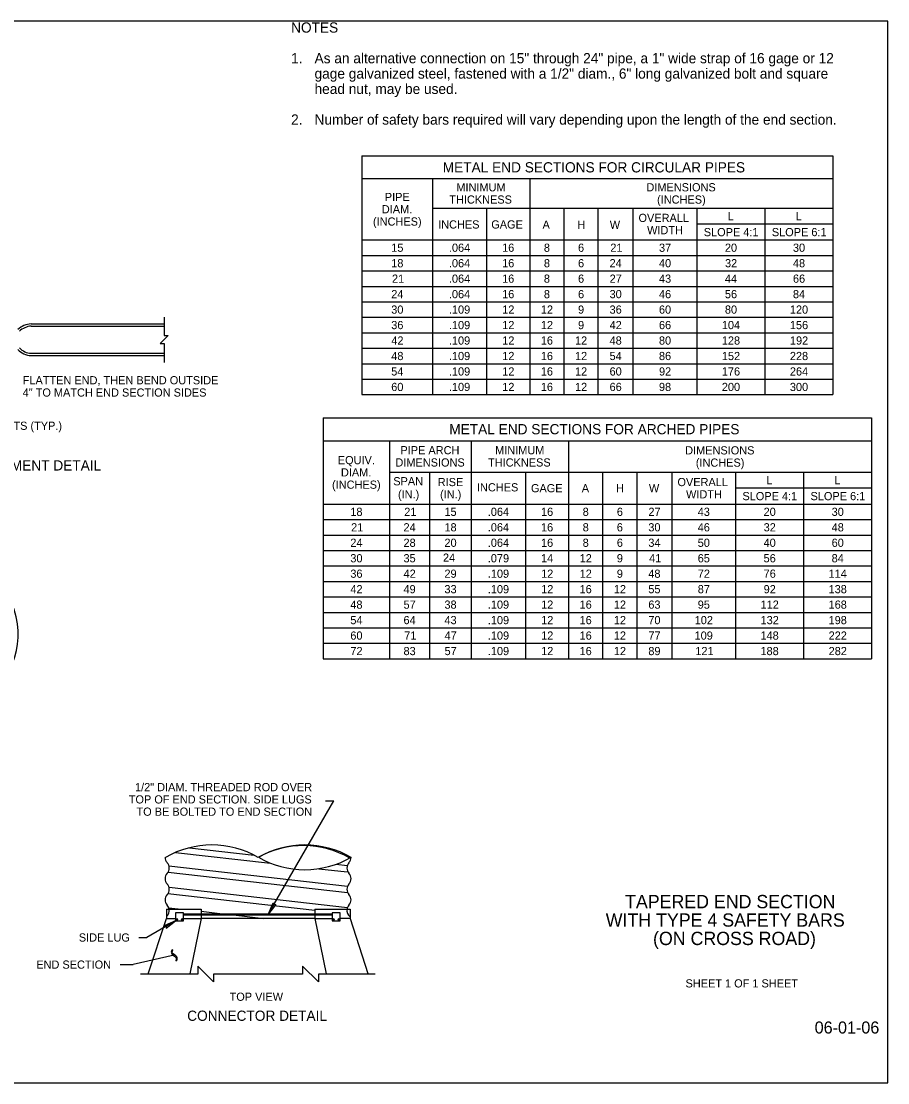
# Model space of a CAD drawing. Extents: x 99862 to 103151, y 100000 to 102076.
# Drawn here: x 101456 to 103151, y 100000 to 102076 of the extents above; entities that cross this region are included whole.
import ezdxf

# ---------------------------------------------------------------- set-up
doc = ezdxf.new("R2010")
doc.units = 0
for name, color, linetype in [('Level 1', 7, 'Continuous'), ('Level 11', 7, 'Continuous'), ('Level 15', 7, 'Continuous'), ('Level 18', 7, 'Continuous'), ('Level 19', 7, 'Continuous'), ('Level 20', 7, 'Continuous'), ('Level 6', 7, 'Continuous'), ('Level 60', 7, 'Continuous'), ('Level 62', 7, 'Continuous'), ('Level 63', 7, 'Continuous')]:
    doc.layers.add(name, color=color, linetype=linetype)

msp = doc.modelspace()

# ---------------------------------------------------------------- linework, layer by layer
at = {"layer": 'Level 1'}
msp.add_lwpolyline([(99862, 99999.5), (103151, 99999.5), (103151, 102075.5), (99862, 102075.5)], close=True, dxfattribs=at)
at = {"layer": 'Level 15'}
for p, q in [((101939.9, 100330), (102067.4, 100550.9)), ((102051.4, 100550.9), (102067.4, 100550.9)), ((101758, 100316.1), (101701.7, 100283.6)), ((101685.7, 100283.6), (101701.7, 100283.6))]:
    msp.add_line(p, q, dxfattribs=at)
for points in [[(101735.4, 101497), (101735.4, 101460.8), (101743.1, 101460.8), (101727.6, 101445.3), (101735.4, 101445.3), (101735.4, 101408)], [(101919.1, 100212.2), (101832, 100212.2), (101832, 100196.7), (101801.1, 100227.7), (101801.1, 100212.2), (101689.5, 100212.2)], [(102148.5, 100212.2), (102037.2, 100212.2), (102037.2, 100196.7), (102006.2, 100227.7), (102006.2, 100212.2), (101919.1, 100212.2)]]:
    msp.add_lwpolyline(points, dxfattribs=at)
for points in [[(101939.9, 100330), (101948.7, 100351.3), (101950.7, 100348.9), (101953.9, 100348.3)], [(101758, 100316.1), (101736.8, 100307.3), (101739.2, 100305.2), (101739.7, 100302.1)]]:
    msp.add_lwpolyline(points, close=True, dxfattribs=at)
at = {"layer": 'Level 18'}
for p, q in [((101475.1, 101483.8), (101734.7, 101483.8)), ((101475.3, 101479.4), (101734.7, 101479.4)), ((101475.1, 101426.2), (101734.7, 101426.2)), ((101475.1, 101421.8), (101734.7, 101421.8)), ((101739.8, 100339.2), (101807.7, 100339.2)), ((101739.8, 100339.2), (101739.8, 100321)), ((101807.7, 100339.2), (101807.7, 100330)), ((102030.3, 100339.2), (102099.4, 100339.2)), ((102030.3, 100339.2), (102030.3, 100330)), ((102099.4, 100339.2), (102099.4, 100321)), ((101704.2, 100212.7), (101739.8, 100321)), ((101773.4, 100330), (102064.3, 100330)), ((101773.4, 100327.6), (102064.3, 100327.6)), ((101807.7, 100321), (101785.8, 100212.5)), ((101807.7, 100327.6), (101807.7, 100321)), ((102030.3, 100327.6), (102030.3, 100321)), ((102030.3, 100321), (102052.2, 100212.5)), ((102099.4, 100321), (102133.7, 100212.9))]:
    msp.add_line(p, q, dxfattribs=at)
for points in [[(101773.4, 100331.6), (101758, 100331.6), (101758, 100316.1), (101773.4, 100316.1)], [(102079.8, 100331.6), (102064.3, 100331.6), (102064.3, 100316.1), (102079.8, 100316.1)]]:
    msp.add_lwpolyline(points, close=True, dxfattribs=at)
for centre, radius, start, end in [((101479, 101439.5), 44.5, 94.9701, 131.9801), ((101479, 101439.5), 40, 94.9701, 131.9801), ((101476.3, 101458.2), 36.5, 222.1687, 268.2497), ((101476.3, 101458.2), 32, 222.1687, 268.2497), ((101760.7, 100318.6), 1.61, 0, 180), ((101760.7, 100318.6), 1.61, 180, 0), ((101770.7, 100318.6), 1.61, 0, 180), ((101770.7, 100318.6), 1.61, 180, 0), ((102067, 100318.6), 1.61, 0, 180), ((102067, 100318.6), 1.61, 180, 0), ((102077.1, 100318.6), 1.61, 0, 180), ((102077.1, 100318.6), 1.61, 180, 0)]:
    msp.add_arc(centre, radius, start, end, dxfattribs=at)
at = {"layer": 'Level 19'}
for p, q in [((102122.4, 101812.4), (103043.6, 101812.4)), ((102122.4, 101812.4), (102122.4, 101345.2)), ((103043.6, 101812.4), (103043.6, 101345.2)), ((102122.4, 101767.8), (103043.6, 101767.8)), ((102260.4, 101767.8), (102260.4, 101345.2)), ((102450.5, 101767.8), (102450.5, 101345.2)), ((102260.4, 101709.7), (103043.6, 101709.7)), ((102365.9, 101709.7), (102365.9, 101345.2)), ((102517.3, 101709.7), (102517.3, 101345.2)), ((102584.1, 101709.7), (102584.1, 101345.2)), ((102652.6, 101709.7), (102652.6, 101345.2)), ((102777.4, 101709.7), (102777.4, 101345.2)), ((102910.7, 101709.7), (102910.7, 101345.2)), ((103043.8, 101678.6), (102777.5, 101678.6)), ((102122.4, 101647.7), (103043.6, 101647.7)), ((102122.4, 101617.5), (103043.6, 101617.5)), ((102122.4, 101587.2), (103043.6, 101587.2)), ((102122.4, 101557), (103043.6, 101557)), ((102122.4, 101526.7), (103043.6, 101526.7)), ((102122.4, 101496.5), (103043.6, 101496.5)), ((102122.4, 101466.2), (103043.6, 101466.2)), ((102122.4, 101436), (103043.6, 101436)), ((102122.4, 101405.7), (103043.6, 101405.7)), ((102122.4, 101375.5), (103043.6, 101375.5)), ((102122.4, 101345.2), (103043.6, 101345.2)), ((102046.6, 101300.2), (102046.6, 100828.7)), ((102046.6, 101300.2), (103119.4, 101300.2)), ((103119.4, 101300.2), (103119.4, 100828.7)), ((102046.6, 101255.2), (103119.4, 101255.2)), ((102176, 101255.2), (102176, 100828.7)), ((102336.2, 101255.2), (102336.2, 100828.7)), ((102526.4, 101255.2), (102526.4, 100828.7)), ((102176, 101193.4), (103119.4, 101193.4)), ((102254.6, 101193.4), (102254.6, 100828.7)), ((102442.4, 101193.4), (102442.4, 100828.7)), ((102593.2, 101193.4), (102593.2, 100828.7)), ((102660, 101193.4), (102660, 100828.7)), ((102728.5, 101193.4), (102728.5, 100828.7)), ((102853.1, 101193.4), (102853.1, 100828.7)), ((102986.3, 101193.4), (102986.3, 100828.7)), ((103119.4, 101162.3), (102853.1, 101162.3)), ((102046.6, 101131.2), (103119.4, 101131.2)), ((102046.6, 101100.9), (103119.4, 101100.9)), ((102046.6, 101070.7), (103119.4, 101070.7)), ((102046.6, 101040.4), (103119.4, 101040.4)), ((102046.6, 101010.2), (103119.4, 101010.2)), ((102046.6, 100979.9), (103119.4, 100979.9)), ((102046.6, 100949.7), (103119.4, 100949.7)), ((102046.6, 100919.4), (103119.4, 100919.4)), ((102046.6, 100889.2), (103119.4, 100889.2)), ((102046.6, 100858.9), (103119.4, 100858.9)), ((102046.6, 100828.7), (103119.4, 100828.7))]:
    msp.add_line(p, q, dxfattribs=at)
at = {"layer": 'Level 20'}
for p, q in [((101749.7, 100257), (101749.4, 100255.2)), ((101749.4, 100255.2), (101749.6, 100253.5)), ((101749.6, 100253.5), (101750.2, 100251.9)), ((101750.4, 100258.8), (101749.7, 100257)), ((101750.2, 100251.9), (101752, 100249.8)), ((101752.2, 100259.8), (101750.4, 100258.8)), ((101751.2, 100255.8), (101751.5, 100257.5)), ((101751.4, 100254.5), (101751.2, 100255.8)), ((101751.9, 100253.2), (101751.4, 100254.5)), ((101751.5, 100257.5), (101752.2, 100259.8)), ((101753.1, 100251.8), (101751.9, 100253.2)), ((101755.2, 100250.3), (101753.1, 100251.8)), ((101758.6, 100248), (101755.2, 100250.3)), ((101649.3, 100230.6), (101674.8, 100230.6)), ((101755.2, 100249), (101674.8, 100230.6)), ((101752, 100249.8), (101755.6, 100247.3)), ((101755.6, 100247.3), (101757.6, 100245.9)), ((101757.6, 100245.9), (101758.5, 100244.7)), ((101759.1, 100241.7), (101758.1, 100238.2)), ((101758.1, 100238.2), (101760, 100239.2)), ((101758.5, 100244.7), (101759, 100243.4)), ((101760.2, 100246.1), (101758.6, 100248)), ((101759, 100243.4), (101759.1, 100241.7)), ((101760, 100239.2), (101760.7, 100241.2)), ((101760.8, 100244.6), (101760.2, 100246.1)), ((101760.7, 100241.2), (101761, 100243)), ((101761, 100243), (101760.8, 100244.6))]:
    msp.add_line(p, q, dxfattribs=at)
at = {"layer": 'Level 6'}
for p, q in [((101784.8, 100459.2), (101911.4, 100444.9)), ((101757.4, 100449.9), (101943.4, 100428.9)), ((101744.9, 100423.5), (102094.3, 100384.1)), ((102038.2, 100418.2), (102093.8, 100411.9)), ((102071.9, 100426.8), (102093.8, 100424.3)), ((101743.1, 100411.4), (102094.3, 100371.7)), ((101745, 100381.8), (102094.1, 100342.3)), ((101743, 100369.6), (102030.3, 100337.2)), ((101744.4, 100341.9), (101768.8, 100339.2)), ((101807.7, 100334.8), (101849.8, 100330)), ((101739.8, 100321), (101758, 100321)), ((101773.4, 100321), (101807.7, 100321)), ((102030.4, 100321), (101807.7, 100321)), ((101871.3, 100327.6), (101929.7, 100321)), ((102030.3, 100321), (102064.3, 100321)), ((102099.4, 100321), (102079.8, 100321))]:
    msp.add_line(p, q, dxfattribs=at)
for centre, radius, start, end in [((101829, 100283.2), 181.4, 60, 120), ((102010.5, 100283.2), 181.4, 60, 120), ((102007.9, 100283), 180.4, 59.8127, 119.2392), ((101752.5, 100440.4), 15.1, 180.0381, 223.1116), ((102010.5, 100597.5), 181.4, 240, 300), ((102086, 100440.4), 15.1, 316.8884, 359.9619), ((101730.4, 100419.5), 15.1, 316.8884, 43.1116), ((102108.1, 100419.5), 15.1, 136.8884, 223.1116), ((101752.5, 100398.8), 15.1, 136.8884, 223.1116), ((102086, 100398.8), 15.1, 316.8884, 43.1116), ((101730.4, 100377.9), 15.1, 316.8884, 43.1116), ((102108.1, 100377.9), 15.1, 136.8884, 223.1116), ((101752.5, 100357.2), 15.1, 136.8884, 223.1116), ((102086, 100357.2), 15.1, 316.8884, 43.1116), ((101730.4, 100336.3), 15.1, 308.3919, 10.768), ((101730.4, 100336.3), 15.1, 10.768, 43.1116), ((102108.1, 100336.5), 15.1, 169.9575, 234.8817), ((102108.1, 100336.5), 15.1, 136.8884, 169.9575)]:
    msp.add_arc(centre, radius, start, end, dxfattribs=at)
msp.add_ellipse((101299.1, 100908.9), major_axis=(-114.1, 124), ratio=0.796016, start_param=2.847597, end_param=5.706242, dxfattribs=at)
at = {"layer": 'Level 60'}
msp.add_line((103151, 102075.5), (103151, 102075.5), dxfattribs=at)

# ---------------------------------------------------------------- texts
at = {"layer": 'Level 11'}
msp.add_text('06-01-06', height=23.62, dxfattribs=at).set_placement((103008, 100095.8))
at = {"layer": 'Level 19'}
for s, height, p in [('METAL END SECTIONS FOR CIRCULAR PIPES', 20, (102280.4, 101779.8)), ('MINIMUM', 16, (102307.1, 101742.8)), ('DIMENSIONS', 16, (102678.9, 101742.8)), ('PIPE', 16, (102167.2, 101723.8)), ('THICKNESS', 16, (102293.3, 101718.8)), ('(INCHES)', 16, (102699.7, 101718.8)), ('DIAM.', 16, (102161.3, 101699.8)), ('(INCHES)', 16, (102144, 101675.8)), ('INCHES', 16, (102271.5, 101670.1)), ('GAGE', 16, (102375.4, 101670.1)), ('A', 16, (102475.7, 101669.7)), ('H', 16, (102543.8, 101669.3)), ('W', 16, (102607.2, 101669.5)), ('OVERALL', 16, (102663.4, 101682.9)), ('L', 16, (102837.8, 101686.2)), ('L', 16, (102970.9, 101686.2)), ('WIDTH', 16, (102680.2, 101658.9)), ('SLOPE 4:1', 16, (102791.1, 101655.1)), ('SLOPE 6:1', 16, (102924.2, 101655.1)), ('15', 16, (102179.7, 101624.6)), ('.064', 16, (102292.5, 101624.6)), ('16', 16, (102396.6, 101624.6)), ('8', 16, (102478.3, 101624.6)), ('6', 16, (102545.1, 101624.6)), ('21', 16, (102608.3, 101624.6)), ('37', 16, (102703.5, 101624.6)), ('20', 16, (102832.4, 101624.6)), ('30', 16, (102965.5, 101624.6)), ('18', 16, (102179.7, 101594.3)), ('.064', 16, (102292.5, 101594.3)), ('16', 16, (102396.6, 101594.3)), ('8', 16, (102478.3, 101594.3)), ('6', 16, (102545.1, 101594.3)), ('24', 16, (102606.8, 101594.3)), ('40', 16, (102703.4, 101594.3)), ('32', 16, (102832.6, 101594.3)), ('48', 16, (102965.5, 101594.3)), ('21', 16, (102181.2, 101564.1)), ('.064', 16, (102292.5, 101564.1)), ('16', 16, (102396.6, 101564.1)), ('8', 16, (102478.3, 101564.1)), ('6', 16, (102545.1, 101564.1)), ('27', 16, (102606.9, 101564.1)), ('43', 16, (102703.4, 101564.1)), ('44', 16, (102832.4, 101564.1)), ('66', 16, (102965.5, 101564.1)), ('24', 16, (102179.7, 101533.8)), ('.064', 16, (102292.5, 101533.8)), ('16', 16, (102396.6, 101533.8)), ('8', 16, (102478.3, 101533.8)), ('6', 16, (102545.1, 101533.8)), ('30', 16, (102606.8, 101533.8)), ('46', 16, (102703.4, 101533.8)), ('56', 16, (102832.4, 101533.8)), ('84', 16, (102965.5, 101533.8)), ('30', 16, (102179.7, 101503.6)), ('.109', 16, (102292.5, 101503.6)), ('12', 16, (102396.8, 101503.6)), ('12', 16, (102472.4, 101503.6)), ('9', 16, (102545.1, 101503.6)), ('36', 16, (102606.8, 101503.6)), ('60', 16, (102703.4, 101503.6)), ('80', 16, (102832.4, 101503.6)), ('120', 16, (102959.5, 101503.6)), ('36', 16, (102179.7, 101473.3)), ('.109', 16, (102292.5, 101473.3)), ('12', 16, (102396.8, 101473.3)), ('12', 16, (102472.4, 101473.3)), ('9', 16, (102545.1, 101473.3)), ('42', 16, (102606.9, 101473.3)), ('66', 16, (102703.4, 101473.3)), ('104', 16, (102826.4, 101473.3)), ('156', 16, (102959.5, 101473.3)), ('42', 16, (102179.9, 101443.1)), ('.109', 16, (102292.5, 101443.1)), ('12', 16, (102396.8, 101443.1)), ('16', 16, (102472.3, 101443.1)), ('12', 16, (102539.2, 101443.1)), ('48', 16, (102606.8, 101443.1)), ('80', 16, (102703.4, 101443.1)), ('128', 16, (102826.4, 101443.1)), ('192', 16, (102959.6, 101443.1)), ('48', 16, (102179.7, 101412.8)), ('.109', 16, (102292.5, 101412.8)), ('12', 16, (102396.8, 101412.8)), ('16', 16, (102472.3, 101412.8)), ('12', 16, (102539.2, 101412.8)), ('54', 16, (102606.8, 101412.8)), ('86', 16, (102703.4, 101412.8)), ('152', 16, (102826.5, 101412.8)), ('228', 16, (102959.5, 101412.8)), ('54', 16, (102179.7, 101382.6)), ('.109', 16, (102292.5, 101382.6)), ('12', 16, (102396.8, 101382.6)), ('16', 16, (102472.3, 101382.6)), ('12', 16, (102539.2, 101382.6)), ('60', 16, (102606.8, 101382.6)), ('92', 16, (102703.5, 101382.6)), ('176', 16, (102826.4, 101382.6)), ('264', 16, (102959.5, 101382.6)), ('60', 16, (102179.7, 101352.3)), ('.109', 16, (102292.5, 101352.3)), ('12', 16, (102396.8, 101352.3)), ('16', 16, (102472.3, 101352.3)), ('12', 16, (102539.2, 101352.3)), ('66', 16, (102606.8, 101352.3)), ('98', 16, (102703.4, 101352.3)), ('200', 16, (102826.4, 101352.3)), ('300', 16, (102959.5, 101352.3)), ('METAL END SECTIONS FOR ARCHED PIPES', 20, (102293.2, 101267.7)), ('PIPE ARCH', 16, (102197.7, 101228.6)), ('MINIMUM', 16, (102383, 101228.6)), ('DIMENSIONS', 16, (102754.7, 101228.3)), ('EQUIV.', 16, (102075.2, 101209.2)), ('DIMENSIONS', 16, (102187.9, 101204.6)), ('THICKNESS', 16, (102369.1, 101204.6)), ('(INCHES)', 16, (102775.5, 101204.3)), ('DIAM.', 16, (102081.3, 101185.2)), ('L', 16, (102913.4, 101169.9)), ('L', 16, (103046.5, 101169.9)), ('(INCHES)', 16, (102063.9, 101161.2)), ('SPAN', 16, (102183.7, 101167.9)), ('RISE', 16, (102270.7, 101166.3)), ('INCHES', 16, (102347.4, 101156)), ('GAGE', 16, (102453, 101154.3)), ('A', 16, (102552.4, 101154.3)), ('H', 16, (102619.5, 101154.3)), ('W', 16, (102683.8, 101154.3)), ('OVERALL', 16, (102739.6, 101166.3)), ('(IN.)', 16, (102192.9, 101142.3)), ('(IN.)', 16, (102275.2, 101142.3)), ('WIDTH', 16, (102756.4, 101142.3)), ('SLOPE 4:1', 16, (102866.7, 101138.8)), ('SLOPE 6:1', 16, (102999.9, 101138.8)), ('18', 16, (102099.7, 101108.1)), ('21', 16, (102205.2, 101108.1)), ('15', 16, (102283.8, 101108.1)), ('.064', 16, (102368.6, 101108.1)), ('16', 16, (102472.7, 101108.1)), ('8', 16, (102554.2, 101108.1)), ('6', 16, (102621, 101108.1)), ('27', 16, (102682.8, 101108.1)), ('43', 16, (102779.2, 101108.1)), ('20', 16, (102908.1, 101108.1)), ('30', 16, (103041.2, 101108.1)), ('21', 16, (102101.2, 101077.8)), ('24', 16, (102203.7, 101077.8)), ('18', 16, (102283.8, 101077.8)), ('.064', 16, (102368.6, 101077.8)), ('16', 16, (102472.7, 101077.8)), ('8', 16, (102554.2, 101077.8)), ('6', 16, (102621, 101077.8)), ('30', 16, (102682.6, 101077.8)), ('46', 16, (102779.2, 101077.8)), ('32', 16, (102908.2, 101077.8)), ('48', 16, (103041.2, 101077.8)), ('24', 16, (102099.7, 101047.6)), ('28', 16, (102203.7, 101047.6)), ('20', 16, (102283.8, 101047.6)), ('.064', 16, (102368.6, 101047.6)), ('16', 16, (102472.7, 101047.6)), ('8', 16, (102554.2, 101047.6)), ('6', 16, (102621, 101047.6)), ('34', 16, (102682.6, 101047.6)), ('50', 16, (102779.2, 101047.6)), ('40', 16, (102908.1, 101047.6)), ('60', 16, (103041.2, 101047.6)), ('30', 16, (102099.7, 101017.3)), ('35', 16, (102203.7, 101017.3)), ('24', 16, (102280.9, 101018.5)), ('.079', 16, (102368.6, 101017.3)), ('14', 16, (102472.7, 101017.3)), ('12', 16, (102548.3, 101017.3)), ('9', 16, (102621, 101017.3)), ('41', 16, (102684.1, 101017.3)), ('65', 16, (102779.2, 101017.3)), ('56', 16, (102908.1, 101017.3)), ('84', 16, (103041.2, 101017.3)), ('36', 16, (102099.7, 100987.1)), ('42', 16, (102203.8, 100987.1)), ('29', 16, (102283.8, 100987.1)), ('.109', 16, (102368.6, 100987.1)), ('12', 16, (102472.9, 100987.1)), ('12', 16, (102548.3, 100987.1)), ('9', 16, (102621, 100987.1)), ('48', 16, (102682.6, 100987.1)), ('72', 16, (102779.3, 100987.1)), ('76', 16, (102908.1, 100987.1)), ('114', 16, (103035.2, 100987.1)), ('42', 16, (102099.8, 100956.8)), ('49', 16, (102203.7, 100956.8)), ('33', 16, (102283.8, 100956.8)), ('.109', 16, (102368.6, 100956.8)), ('12', 16, (102472.9, 100956.8)), ('16', 16, (102548.1, 100956.8)), ('12', 16, (102615.1, 100956.8)), ('55', 16, (102682.6, 100956.8)), ('87', 16, (102779.3, 100956.8)), ('92', 16, (102908.2, 100956.8)), ('138', 16, (103035.2, 100956.8)), ('48', 16, (102099.7, 100926.6)), ('57', 16, (102203.8, 100926.6)), ('38', 16, (102283.8, 100926.6)), ('.109', 16, (102368.6, 100926.6)), ('12', 16, (102472.9, 100926.6)), ('16', 16, (102548.1, 100926.6)), ('12', 16, (102615.1, 100926.6)), ('63', 16, (102682.6, 100926.6)), ('95', 16, (102779.2, 100926.6)), ('112', 16, (102902.2, 100926.6)), ('168', 16, (103035.2, 100926.6)), ('54', 16, (102099.7, 100896.3)), ('64', 16, (102203.7, 100896.3)), ('43', 16, (102283.8, 100896.3)), ('.109', 16, (102368.6, 100896.3)), ('12', 16, (102472.9, 100896.3)), ('16', 16, (102548.1, 100896.3)), ('12', 16, (102615.1, 100896.3)), ('70', 16, (102682.6, 100896.3)), ('102', 16, (102773.3, 100896.3)), ('132', 16, (102902.2, 100896.3)), ('198', 16, (103035.2, 100896.3)), ('60', 16, (102099.7, 100866.1)), ('71', 16, (102205.2, 100866.1)), ('47', 16, (102284, 100866.1)), ('.109', 16, (102368.6, 100866.1)), ('12', 16, (102472.9, 100866.1)), ('16', 16, (102548.1, 100866.1)), ('12', 16, (102615.1, 100866.1)), ('77', 16, (102682.8, 100866.1)), ('109', 16, (102773.1, 100866.1)), ('148', 16, (102902, 100866.1)), ('222', 16, (103035.3, 100866.1)), ('72', 16, (102099.8, 100835.8)), ('83', 16, (102203.7, 100835.8)), ('57', 16, (102284, 100835.8)), ('.109', 16, (102368.6, 100835.8)), ('12', 16, (102472.9, 100835.8)), ('16', 16, (102548.1, 100835.8)), ('12', 16, (102615.1, 100835.8)), ('89', 16, (102682.6, 100835.8)), ('121', 16, (102774.6, 100835.8)), ('188', 16, (102902, 100835.8)), ('282', 16, (103035.3, 100835.8))]:
    msp.add_text(s, height=height, dxfattribs=at).set_placement(p)
at = {"layer": 'Level 20'}
for s, height, p in [('NOTES', 20, (101983.8, 102053.2)), ('1.', 20, (101983.8, 101993.2)), ('As an alternative connection on 15" through 24" pipe, a 1" wide strap of 16 gage or 12', 20, (102029.7, 101993.2)), ('gage galvanized steel, fastened with a 1/2" diam., 6" long galvanized bolt and square', 20, (102029.7, 101963.2)), ('head nut, may be used.', 20, (102029.7, 101933.2)), ('2.', 20, (101983.8, 101873.2)), ('Number of safety bars required will vary depending upon the length of the end section.', 20, (102029.7, 101873.2)), ('FLATTEN END, THEN BEND OUTSIDE', 16, (101458.8, 101365.4)), ('4" TO MATCH END SECTION SIDES', 16, (101458.8, 101341.4)), ('9/16" x 1" SLOTS (TYP.)', 16, (101300.6, 101276.4)), ('SAFETY BAR END TREATMENT DETAIL', 20, (101110.1, 101196.8)), ('1/2" DIAM. THREADED ROD OVER', 16, (101678.5, 100569.7)), ('TOP OF END SECTION. SIDE LUGS', 16, (101666.3, 100545.7)), ('TO BE BOLTED TO END SECTION', 16, (101681.4, 100521.7)), ('SIDE LUG', 16, (101568.6, 100275.6)), ('END SECTION', 16, (101485.4, 100222.6)), ('TOP VIEW', 16, (101863.5, 100159.8)), ('CONNECTOR DETAIL', 20, (101780.6, 100120.6))]:
    msp.add_text(s, height=height, dxfattribs=at).set_placement(p)
at = {"layer": 'Level 62'}
msp.add_text('SHEET 1 OF 1 SHEET', height=16, dxfattribs=at).set_placement((102755.4, 100185.9))
msp.add_text('SHEET 1 OF 1 SHEET', height=16, dxfattribs=at).set_placement((102755.4, 100185.9))
at = {"layer": 'Level 63'}
for s, p in [('TAPERED END SECTION', (102637.1, 100340.8)), ('WITH TYPE 4 SAFETY BARS', (102599.3, 100304.8)), ('(ON CROSS ROAD)', (102691.8, 100268.8))]:
    msp.add_text(s, height=26, dxfattribs=at).set_placement(p)

doc.saveas('drawing.dxf')
